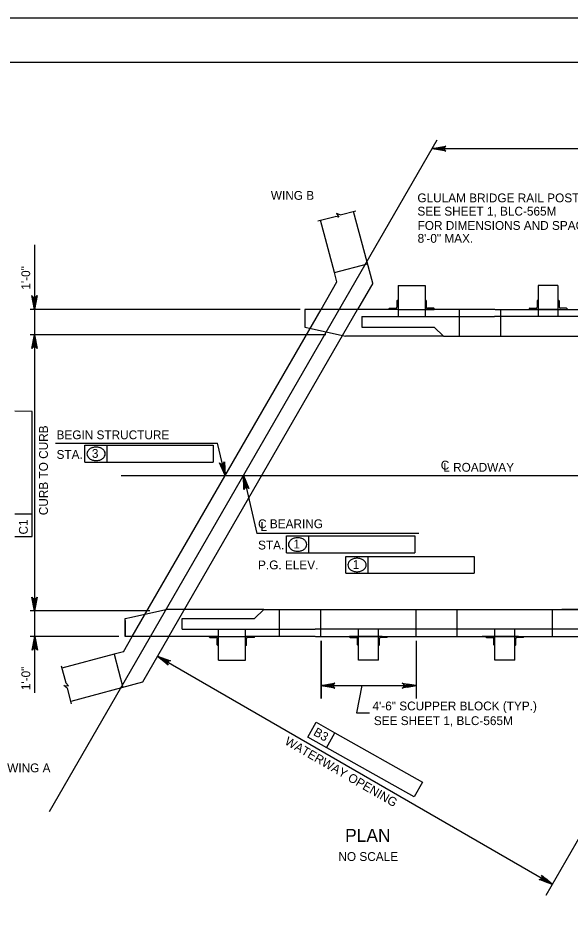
# Model space of a CAD drawing. Extents: x 638268 to 640277, y 295465 to 298435.
# Drawn here: x 638488.1 to 638675.9, y 298131.1 to 298435.5 of the extents above; entities that cross this region are included whole.
import ezdxf

# ---------------------------------------------------------------- set-up
doc = ezdxf.new("R2010")
doc.units = 0
for name, color, linetype in [('2', 7, 'Continuous'), ('3', 7, 'Continuous'), ('4', 7, 'Continuous'), ('PLT-BNDY', 7, 'Continuous')]:
    doc.layers.add(name, color=color, linetype=linetype)

msp = doc.modelspace()

# ---------------------------------------------------------------- linework, layer by layer
at = {"layer": '2'}
for p, q in [((638475.46, 298420.46), (639261.46, 298420.46)), ((638608.8, 298345.27), (638602.26, 298369.68)), ((638595.78, 298348.87), (638591.01, 298366.66)), ((638595.78, 298348.87), (638607.02, 298351.89)), ((638596.62, 298345.72), (638595.78, 298348.87)), ((638591.22, 298336.37), (638596.62, 298345.72)), ((638608.8, 298345.27), (638603.66, 298336.37)), ((638617.4, 298344.46), (638626.64, 298344.46)), ((638617.4, 298344.46), (638617.4, 298333.98)), ((638626.64, 298344.46), (638626.64, 298333.98)), ((638671.79, 298344.46), (638665.07, 298344.46)), ((638665.07, 298344.46), (638665.07, 298333.98)), ((638671.79, 298344.46), (638671.79, 298333.98)), ((638617.04, 298339.28), (638617.04, 298337.1)), ((638617.22, 298339.46), (638617.4, 298339.46)), ((638617.4, 298339.46), (638617.4, 298336.37)), ((638626.82, 298339.46), (638626.64, 298339.46)), ((638626.64, 298339.46), (638626.64, 298336.37)), ((638627, 298339.28), (638627, 298337.1)), ((638664.7, 298339.28), (638664.7, 298337.1)), ((638664.89, 298339.46), (638665.07, 298339.46)), ((638665.07, 298339.46), (638665.07, 298336.37)), ((638671.98, 298339.46), (638671.79, 298339.46)), ((638671.79, 298339.46), (638671.79, 298336.37)), ((638672.16, 298339.28), (638672.16, 298337.1)), ((638527.04, 298225.2), (638591.22, 298336.37)), ((638539.47, 298225.2), (638603.66, 298336.37)), ((638585.66, 298336.37), (638585.66, 298330.34)), ((638617.4, 298336.37), (638585.66, 298336.37)), ((638614.31, 298336.55), (638614.31, 298336.37)), ((638617.4, 298336.37), (638614.31, 298336.37)), ((638614.49, 298336.73), (638616.68, 298336.73)), ((638617.4, 298336.37), (638626.64, 298336.37)), ((638626.64, 298336.37), (638629.73, 298336.37)), ((638650.35, 298336.37), (638626.64, 298336.37)), ((638629.55, 298336.73), (638627.37, 298336.73)), ((638629.73, 298336.55), (638629.73, 298336.37)), ((638638.19, 298336.37), (638638.19, 298327.25)), ((638650.43, 298336.37), (638797.52, 298336.37)), ((638652.26, 298336.37), (638652.26, 298327.25)), ((638661.98, 298336.55), (638661.98, 298336.37)), ((638665.07, 298336.37), (638661.98, 298336.37)), ((638662.16, 298336.73), (638664.34, 298336.73)), ((638671.79, 298336.37), (638665.07, 298336.37)), ((638671.79, 298336.37), (638674.88, 298336.37)), ((638674.7, 298336.73), (638672.52, 298336.73)), ((638674.88, 298336.55), (638674.88, 298336.37)), ((638605.08, 298333.98), (638650.25, 298333.98)), ((638605.08, 298333.98), (638605.08, 298330.34)), ((638778.1, 298333.98), (638650.25, 298333.98)), ((638585.66, 298330.34), (638587.83, 298329.86)), ((638587.83, 298329.86), (638599.51, 298327.25)), ((638605.08, 298330.34), (638629.72, 298330.34)), ((638632.81, 298327.25), (638629.72, 298330.34)), ((638632.81, 298327.25), (638599.51, 298327.25)), ((638632.81, 298327.25), (638648.97, 298327.25)), ((638632.81, 298327.25), (638783.67, 298327.25)), ((638524.57, 298231.23), (638526.74, 298231.71)), ((638526.74, 298231.71), (638538.42, 298234.32)), ((638571.72, 298234.32), (638538.42, 298234.32)), ((638571.72, 298234.32), (638568.63, 298231.23)), ((638571.72, 298234.32), (638587.88, 298234.32)), ((638571.72, 298234.32), (638722.58, 298234.32)), ((638577.1, 298225.2), (638577.1, 298234.32)), ((638591.17, 298225.2), (638591.17, 298234.32)), ((638623.51, 298225.2), (638623.51, 298234.32)), ((638637.53, 298225.2), (638637.53, 298234.32)), ((638669.87, 298225.2), (638669.87, 298234.32)), ((638689.28, 298234.32), (638673.12, 298234.32)), ((638524.57, 298225.2), (638524.57, 298231.23)), ((638524.57, 298230.58), (638524.57, 298225.2)), ((638543.99, 298231.23), (638568.63, 298231.23)), ((638543.99, 298227.59), (638543.99, 298231.23)), ((638543.99, 298227.59), (638589.17, 298227.59)), ((638556.31, 298217.11), (638556.31, 298227.59)), ((638565.55, 298217.11), (638565.55, 298227.59)), ((638717.01, 298227.59), (638589.17, 298227.59)), ((638603.98, 298217.11), (638603.98, 298227.59)), ((638610.7, 298217.11), (638610.7, 298227.59)), ((638650.34, 298217.11), (638650.34, 298227.59)), ((638657.07, 298217.11), (638657.07, 298227.59)), ((638524.01, 298219.94), (638527.04, 298225.2)), ((638524.01, 298219.94), (638527.04, 298225.2)), ((638556.31, 298225.2), (638524.57, 298225.2)), ((638539.47, 298225.2), (638530.48, 298209.63)), ((638553.22, 298225.02), (638553.22, 298225.2)), ((638556.31, 298225.2), (638553.22, 298225.2)), ((638553.4, 298224.83), (638555.59, 298224.83)), ((638555.95, 298222.29), (638555.95, 298224.47)), ((638556.31, 298225.2), (638565.55, 298225.2)), ((638556.31, 298222.11), (638556.31, 298225.2)), ((638565.55, 298225.2), (638568.64, 298225.2)), ((638589.26, 298225.2), (638565.55, 298225.2)), ((638565.55, 298222.11), (638565.55, 298225.2)), ((638565.91, 298222.29), (638565.91, 298224.47)), ((638568.46, 298224.83), (638566.28, 298224.83)), ((638568.64, 298225.02), (638568.64, 298225.2)), ((638589.34, 298225.2), (638736.43, 298225.2)), ((638600.89, 298225.02), (638600.89, 298225.2)), ((638603.98, 298225.2), (638600.89, 298225.2)), ((638601.07, 298224.83), (638603.25, 298224.83)), ((638611.96, 298225.2), (638602.72, 298225.2)), ((638603.61, 298222.29), (638603.61, 298224.47)), ((638610.7, 298225.2), (638603.98, 298225.2)), ((638603.98, 298222.11), (638603.98, 298225.2)), ((638610.7, 298222.11), (638610.7, 298225.2)), ((638610.7, 298225.2), (638613.8, 298225.2)), ((638611.07, 298222.29), (638611.07, 298224.47)), ((638613.61, 298224.83), (638611.43, 298224.83)), ((638613.8, 298225.02), (638613.8, 298225.2)), ((638649.09, 298225.2), (638645.99, 298225.2)), ((638647.25, 298225.02), (638647.25, 298225.2)), ((638650.34, 298225.2), (638647.25, 298225.2)), ((638647.43, 298224.83), (638649.61, 298224.83)), ((638658.32, 298225.2), (638649.09, 298225.2)), ((638658.32, 298225.2), (638649.09, 298225.2)), ((638649.98, 298222.29), (638649.98, 298224.47)), ((638657.07, 298225.2), (638650.34, 298225.2)), ((638650.34, 298222.11), (638650.34, 298225.2)), ((638657.07, 298222.11), (638657.07, 298225.2)), ((638657.07, 298225.2), (638660.16, 298225.2)), ((638657.43, 298222.29), (638657.43, 298224.47)), ((638659.98, 298224.83), (638657.8, 298224.83)), ((638658.32, 298225.2), (638661.41, 298225.2)), ((638660.16, 298225.02), (638660.16, 298225.2)), ((638524.01, 298219.94), (638520.85, 298219.1)), ((638524.01, 298219.94), (638520.85, 298219.1)), ((638556.13, 298222.11), (638556.31, 298222.11)), ((638565.73, 298222.11), (638565.55, 298222.11)), ((638603.8, 298222.11), (638603.98, 298222.11)), ((638610.89, 298222.11), (638610.7, 298222.11)), ((638650.16, 298222.11), (638650.34, 298222.11)), ((638657.25, 298222.11), (638657.07, 298222.11)), ((638520.85, 298219.1), (638503.06, 298214.33)), ((638520.85, 298219.1), (638523.87, 298207.86)), ((638556.31, 298217.11), (638565.55, 298217.11)), ((638610.7, 298217.11), (638603.98, 298217.11)), ((638610.7, 298217.11), (638603.98, 298217.11)), ((638657.07, 298217.11), (638650.34, 298217.11)), ((638657.07, 298217.11), (638650.34, 298217.11)), ((638657.07, 298217.11), (638650.34, 298217.11)), ((638530.48, 298209.63), (638506.08, 298203.09))]:
    msp.add_line(p, q, dxfattribs=at)
for centre, radius, start, end in [((638617.22, 298339.28), 0.182, 90, 179.9984), ((638626.82, 298339.28), 0.182, 0.0016, 90), ((638664.89, 298339.28), 0.182, 90, 179.9984), ((638671.98, 298339.28), 0.182, 0.0016, 90), ((638614.49, 298336.55), 0.182, 90, 179.9984), ((638616.68, 298337.1), 0.364, 270, 359.9984), ((638627.37, 298337.1), 0.364, 180.0016, 270), ((638629.55, 298336.55), 0.182, 0.0016, 90), ((638662.16, 298336.55), 0.182, 90, 179.9984), ((638664.34, 298337.1), 0.364, 270, 359.9984), ((638672.52, 298337.1), 0.364, 180.0016, 270), ((638674.7, 298336.55), 0.182, 0.0016, 90), ((638553.4, 298225.02), 0.182, 180.0016, 270), ((638555.59, 298224.47), 0.364, 0.0016, 90), ((638566.28, 298224.47), 0.364, 90, 179.9984), ((638568.46, 298225.02), 0.182, 270, 359.9984), ((638601.07, 298225.02), 0.182, 180.0016, 270), ((638603.25, 298224.47), 0.364, 0.0016, 90), ((638611.43, 298224.47), 0.364, 90, 179.9984), ((638613.61, 298225.02), 0.182, 270, 359.9984), ((638647.43, 298225.02), 0.182, 180.0016, 270), ((638649.61, 298224.47), 0.364, 0.0016, 90), ((638657.8, 298224.47), 0.364, 90, 179.9984), ((638659.98, 298225.02), 0.182, 270, 359.9984), ((638556.13, 298222.29), 0.182, 180.0016, 270), ((638565.73, 298222.29), 0.182, 270, 359.9984), ((638603.8, 298222.29), 0.182, 180.0016, 270), ((638610.89, 298222.29), 0.182, 270, 359.9984), ((638650.16, 298222.29), 0.182, 180.0016, 270), ((638657.25, 298222.29), 0.182, 270, 359.9984)]:
    msp.add_arc(centre, radius, start, end, dxfattribs=at)
at = {"layer": '3'}
for p, q in [((638498.88, 298165.66), (638630.71, 298394)), ((638596.46, 298369), (638597.32, 298367.7)), ((638597.71, 298368.46), (638596.46, 298369)), ((638597.71, 298368.46), (638603.05, 298369.89)), ((638590.14, 298366.43), (638595.98, 298367.99)), ((638597.32, 298367.7), (638595.98, 298367.99)), ((638502.83, 298215.2), (638504.39, 298209.37)), ((638504.86, 298207.63), (638503.76, 298208.45)), ((638503.76, 298208.45), (638505.32, 298208.36)), ((638505.32, 298208.36), (638504.39, 298209.37)), ((638504.86, 298207.63), (638506.29, 298202.29))]:
    msp.add_line(p, q, dxfattribs=at)
at = {"layer": '4'}
for p, q in [((638628.98, 298391), (638820.39, 298391)), ((638493.78, 298358.26), (638493.78, 298205.98)), ((638584.09, 298336.37), (638492.34, 298336.37)), ((638592.81, 298327.72), (638492.34, 298327.72)), ((638492.94, 298301.69), (638487.04, 298301.7)), ((638492.94, 298259.17), (638492.94, 298301.69)), ((638500.9, 298290.93), (638555.97, 298290.93)), ((638510.95, 298284.4), (638510.95, 298290.17)), ((638510.95, 298290.17), (638518.53, 298290.17)), ((638518.53, 298284.4), (638518.53, 298290.17)), ((638518.53, 298290.17), (638554.54, 298290.17)), ((638554.54, 298290.17), (638554.54, 298284.4)), ((638558.58, 298279.83), (638555.97, 298290.93)), ((638510.95, 298284.4), (638554.54, 298284.4)), ((638523.29, 298279.83), (638808.3, 298279.83)), ((638564.8, 298279.83), (638569.42, 298260.13)), ((638492.94, 298266.73), (638487.04, 298266.74)), ((638487.04, 298259.18), (638492.94, 298259.17)), ((638624.5, 298260.13), (638569.42, 298260.13)), ((638579.47, 298259.36), (638587.05, 298259.36)), ((638579.47, 298253.6), (638579.47, 298259.36)), ((638587.05, 298253.6), (638587.05, 298259.36)), ((638587.05, 298259.36), (638623.06, 298259.36)), ((638623.06, 298259.36), (638623.06, 298253.6)), ((638579.47, 298253.6), (638623.06, 298253.6)), ((638599.66, 298246.63), (638599.66, 298252.4)), ((638599.66, 298252.4), (638607.24, 298252.4)), ((638607.24, 298246.63), (638607.24, 298252.4)), ((638607.24, 298252.4), (638643.25, 298252.4)), ((638643.25, 298252.4), (638643.25, 298246.63)), ((638599.66, 298246.63), (638643.25, 298246.63)), ((638533.01, 298233.85), (638492.34, 298233.85)), ((638522.43, 298225.2), (638492.34, 298225.2)), ((638591.17, 298223.66), (638591.17, 298204.02)), ((638591.27, 298223.66), (638591.27, 298204.02)), ((638623.51, 298223.66), (638623.51, 298204.02)), ((638535.58, 298218.46), (638669.81, 298140.96)), ((638712.54, 298214.97), (638667.6, 298137.13)), ((638591.17, 298208.45), (638623.51, 298208.45)), ((638591.27, 298208.45), (638618.98, 298208.45)), ((638605.12, 298208.45), (638603.28, 298199.23)), ((638605.12, 298208.45), (638603.28, 298199.23)), ((638603.28, 298199.23), (638607.71, 298199.23)), ((638603.28, 298199.23), (638607.71, 298199.23)), ((638586.68, 298190.95), (638589.51, 298195.97)), ((638589.51, 298195.97), (638595.91, 298192.37)), ((638593.09, 298187.35), (638595.91, 298192.37)), ((638595.91, 298192.37), (638625.7, 298175.63)), ((638622.88, 298170.6), (638586.68, 298190.95)), ((638625.7, 298175.63), (638622.88, 298170.6))]:
    msp.add_line(p, q, dxfattribs=at)
for points in [[(638628.98, 298391), (638633.64, 298391.87), (638633.28, 298391.62), (638633.09, 298391.31), (638633.04, 298391), (638633.09, 298390.68), (638633.28, 298390.37), (638633.64, 298390.12), (638628.98, 298391), (638633.28, 298390.37), (638633.09, 298390.68), (638628.98, 298391), (638633.04, 298391), (638633.09, 298391.31), (638628.98, 298391), (638633.28, 298391.62)], [(638493.78, 298336.37), (638492.9, 298341.03), (638493.15, 298340.67), (638493.46, 298340.49), (638493.78, 298340.44), (638494.09, 298340.49), (638494.4, 298340.67), (638494.65, 298341.03), (638493.78, 298336.37), (638494.4, 298340.67), (638494.09, 298340.49), (638493.78, 298336.37), (638493.78, 298340.44), (638493.46, 298340.49), (638493.78, 298336.37), (638493.15, 298340.67)], [(638493.78, 298327.72), (638494.65, 298323.06), (638494.4, 298323.42), (638494.09, 298323.6), (638493.78, 298323.66), (638493.46, 298323.6), (638493.15, 298323.42), (638492.9, 298323.06), (638493.78, 298327.72), (638493.15, 298323.42), (638493.46, 298323.6), (638493.78, 298327.72), (638493.78, 298323.66), (638494.09, 298323.6), (638493.78, 298327.72), (638494.4, 298323.42)], [(638558.58, 298279.83), (638556.66, 298284.17), (638556.99, 298283.87), (638557.34, 298283.77), (638557.65, 298283.78), (638557.94, 298283.91), (638558.21, 298284.16), (638558.37, 298284.57), (638558.58, 298279.83), (638558.21, 298284.16), (638557.94, 298283.91), (638558.58, 298279.83), (638557.65, 298283.78), (638557.34, 298283.77), (638558.58, 298279.83), (638556.99, 298283.87)], [(638564.8, 298279.83), (638566.71, 298275.49), (638566.39, 298275.79), (638566.04, 298275.9), (638565.72, 298275.88), (638565.43, 298275.75), (638565.17, 298275.5), (638565.01, 298275.09), (638564.8, 298279.83), (638565.17, 298275.5), (638565.43, 298275.75), (638564.8, 298279.83), (638565.72, 298275.88), (638566.04, 298275.9), (638564.8, 298279.83), (638566.39, 298275.79)], [(638493.78, 298233.85), (638492.9, 298238.51), (638493.15, 298238.15), (638493.46, 298237.97), (638493.78, 298237.91), (638494.09, 298237.97), (638494.4, 298238.15), (638494.65, 298238.51), (638493.78, 298233.85), (638494.4, 298238.15), (638494.09, 298237.97), (638493.78, 298233.85), (638493.78, 298237.91), (638493.46, 298237.97), (638493.78, 298233.85), (638493.15, 298238.15)], [(638493.89, 298225.18), (638494.76, 298220.52), (638494.51, 298220.88), (638494.2, 298221.07), (638493.89, 298221.12), (638493.57, 298221.07), (638493.26, 298220.88), (638493.01, 298220.52), (638493.89, 298225.18), (638493.26, 298220.88), (638493.57, 298221.07), (638493.89, 298225.18), (638493.89, 298221.12), (638494.2, 298221.07), (638493.89, 298225.18), (638494.51, 298220.88)], [(638535.58, 298218.46), (638540.05, 298216.89), (638539.62, 298216.85), (638539.3, 298216.67), (638539.1, 298216.43), (638538.99, 298216.13), (638538.99, 298215.77), (638539.18, 298215.37), (638535.58, 298218.46), (638538.99, 298215.77), (638538.99, 298216.13), (638535.58, 298218.46), (638539.1, 298216.43), (638539.3, 298216.67), (638535.58, 298218.46), (638539.62, 298216.85)], [(638535.58, 298218.46), (638540.05, 298216.89), (638539.62, 298216.85), (638539.3, 298216.67), (638539.1, 298216.43), (638538.99, 298216.13), (638538.99, 298215.77), (638539.18, 298215.37), (638535.58, 298218.46), (638538.99, 298215.77), (638538.99, 298216.13), (638535.58, 298218.46), (638539.1, 298216.43), (638539.3, 298216.67), (638535.58, 298218.46), (638539.62, 298216.85)], [(638591.17, 298208.45), (638595.83, 298209.32), (638595.47, 298209.08), (638595.29, 298208.76), (638595.23, 298208.45), (638595.29, 298208.14), (638595.47, 298207.83), (638595.83, 298207.58), (638591.17, 298208.45), (638595.47, 298207.83), (638595.29, 298208.14), (638591.17, 298208.45), (638595.23, 298208.45), (638595.29, 298208.76), (638591.17, 298208.45), (638595.47, 298209.08)], [(638591.27, 298208.45), (638595.93, 298209.32), (638595.57, 298209.08), (638595.39, 298208.76), (638595.34, 298208.45), (638595.39, 298208.14), (638595.57, 298207.83), (638595.93, 298207.58), (638591.27, 298208.45), (638595.57, 298207.83), (638595.39, 298208.14), (638591.27, 298208.45), (638595.34, 298208.45), (638595.39, 298208.76), (638591.27, 298208.45), (638595.57, 298209.08)], [(638623.51, 298208.45), (638618.85, 298207.58), (638619.21, 298207.83), (638619.39, 298208.14), (638619.45, 298208.45), (638619.39, 298208.76), (638619.21, 298209.08), (638618.85, 298209.32), (638623.51, 298208.45), (638619.21, 298209.08), (638619.39, 298208.76), (638623.51, 298208.45), (638619.45, 298208.45), (638619.39, 298208.14), (638623.51, 298208.45), (638619.21, 298207.83)], [(638669.81, 298140.96), (638665.34, 298142.53), (638665.78, 298142.57), (638666.09, 298142.75), (638666.29, 298142.99), (638666.4, 298143.29), (638666.4, 298143.65), (638666.21, 298144.05), (638669.81, 298140.96), (638666.4, 298143.65), (638666.4, 298143.29), (638669.81, 298140.96), (638666.29, 298142.99), (638666.09, 298142.75), (638669.81, 298140.96), (638665.78, 298142.57)]]:
    msp.add_lwpolyline(points, dxfattribs=at)
for points in [[(638493.3, 298339.26), (638494.26, 298339.26), (638493.78, 298336.37)], [(638493.3, 298324.84), (638494.26, 298324.84), (638493.78, 298327.72)], [(638564.99, 298276.84), (638565.95, 298277.07), (638564.8, 298279.83)], [(638493.3, 298236.73), (638494.26, 298236.73), (638493.78, 298233.85)], [(638493.3, 298222.31), (638494.26, 298222.31), (638493.78, 298225.2)], [(638594.13, 298208.95), (638594.13, 298207.96), (638591.17, 298208.45)], [(638594.23, 298208.95), (638594.23, 298207.96), (638591.27, 298208.45)], [(638620.56, 298208.95), (638620.56, 298207.96), (638623.51, 298208.45)], [(638667.5, 298142.87), (638667.01, 298142.01), (638669.81, 298140.96)]]:
    msp.add_lwpolyline(points, close=True, dxfattribs=at)
for centre, radius, start, end in [((638514.45, 298286.26), 3.23, 106.9552, 126.3544), ((638514.74, 298285.31), 4.22, 90, 106.9552), ((638514.74, 298285.31), 4.22, 73.0448, 90), ((638515.02, 298286.26), 3.23, 53.6456, 73.0448), ((638513.33, 298287.24), 1.71, 150.6308, 180), ((638513.33, 298287.24), 1.71, 180, 209.3692), ((638514.01, 298286.86), 2.49, 126.3544, 150.6308), ((638514.01, 298287.62), 2.49, 209.3692, 233.6456), ((638515.47, 298286.86), 2.49, 29.3692, 53.6456), ((638515.47, 298287.62), 2.49, 306.3544, 330.6308), ((638516.14, 298287.24), 1.71, 0, 29.3692), ((638516.14, 298287.24), 1.71, 330.6308, 0), ((638514.45, 298288.22), 3.23, 233.6456, 253.0448), ((638514.74, 298289.16), 4.22, 253.0448, 270), ((638514.74, 298289.16), 4.22, 270, 286.9552), ((638515.02, 298288.22), 3.23, 286.9552, 306.3544), ((638581.85, 298256.43), 1.71, 150.6308, 180), ((638581.85, 298256.43), 1.71, 180, 209.3692), ((638582.53, 298256.05), 2.49, 126.3544, 150.6308), ((638582.97, 298255.45), 3.23, 106.9552, 126.3544), ((638583.26, 298254.51), 4.22, 90, 106.9552), ((638583.26, 298254.51), 4.22, 73.0448, 90), ((638583.54, 298255.45), 3.23, 53.6456, 73.0448), ((638583.99, 298256.05), 2.49, 29.3692, 53.6456), ((638584.66, 298256.43), 1.71, 0, 29.3692), ((638584.66, 298256.43), 1.71, 330.6308, 0), ((638582.53, 298256.81), 2.49, 209.3692, 233.6456), ((638582.97, 298257.41), 3.23, 233.6456, 253.0448), ((638583.26, 298258.36), 4.22, 253.0448, 270), ((638583.26, 298258.36), 4.22, 270, 286.9552), ((638583.54, 298257.41), 3.23, 286.9552, 306.3544), ((638583.99, 298256.81), 2.49, 306.3544, 330.6308), ((638602.04, 298249.47), 1.71, 150.6308, 180), ((638602.72, 298249.09), 2.49, 126.3544, 150.6308), ((638603.16, 298248.49), 3.23, 106.9552, 126.3544), ((638603.45, 298247.54), 4.22, 90, 106.9552), ((638603.45, 298247.54), 4.22, 73.0448, 90), ((638603.73, 298248.49), 3.23, 53.6456, 73.0448), ((638604.18, 298249.09), 2.49, 29.3692, 53.6456), ((638604.85, 298249.47), 1.71, 0, 29.3692), ((638602.04, 298249.47), 1.71, 180, 209.3692), ((638602.72, 298249.85), 2.49, 209.3692, 233.6456), ((638603.16, 298250.45), 3.23, 233.6456, 253.0448), ((638603.45, 298251.39), 4.22, 253.0448, 270), ((638603.45, 298251.39), 4.22, 270, 286.9552), ((638603.73, 298250.45), 3.23, 286.9552, 306.3544), ((638604.18, 298249.85), 2.49, 306.3544, 330.6308), ((638604.85, 298249.47), 1.71, 330.6308, 0)]:
    msp.add_arc(centre, radius, start, end, dxfattribs=at)
at = {"layer": 'PLT-BNDY'}
msp.add_lwpolyline([(638435.46, 298435.46), (639276.46, 298435.46), (639276.46, 297841.46), (638435.46, 297841.46)], close=True, dxfattribs=at)

# ---------------------------------------------------------------- texts
at = {"layer": '4'}
for s, height, p in [('WING B', 3, (638574.15, 298373.61)), ('GLULAM BRIDGE RAIL POST (TYP.)', 3, (638623.99, 298372.76)), ('SEE SHEET 1, BLC-565M', 3, (638623.99, 298368.24)), ('FOR DIMENSIONS AND SPACINGS', 3, (638624.05, 298363.39)), ('8\'-0" MAX.', 3, (638624.05, 298359.01)), ('BEGIN STRUCTURE', 3, (638501.28, 298292.21)), ('STA.', 3, (638501.28, 298285.54)), ('3', 3, (638513.29, 298285.89)), ('C', 3, (638631.92, 298281.91)), ('L ROADWAY', 3, (638632.78, 298281.17)), ('C BEARING', 3, (638569.8, 298261.97)), ('L', 3, (638570.62, 298261.06)), ('STA.', 3, (638569.8, 298254.73)), ('1', 3, (638581.81, 298255.08)), ('P.G. ELEV.', 3, (638569.8, 298247.98)), ('1', 3, (638601.99, 298248.12)), ('4\'-6" SCUPPER BLOCK (TYP.)', 3, (638608.71, 298200.03)), ('SEE SHEET 1, BLC-565M', 3, (638609.17, 298195.03)), ('WING A', 3, (638484.5, 298178.98)), ('PLAN', 4.429, (638599.39, 298155.32)), ('NO SCALE', 3, (638597.12, 298148.84))]:
    msp.add_text(s, height=height, dxfattribs=at).set_placement(p)
for s, rotation, p in [('1\'-0"', 90, (638492.32, 298343.06)), ('CURB TO CURB', 90, (638498.33, 298266.38)), ('C1', 89.9382, (638491.49, 298259.83)), ('1\'-0"', 90, (638492.32, 298206.91)), ('B3', 330.6611, (638588.36, 298191.75)), ('WATERWAY OPENING', 330, (638578.61, 298188.68))]:
    msp.add_text(s, height=3, rotation=rotation, dxfattribs=at).set_placement(p)

doc.saveas('drawing.dxf')
